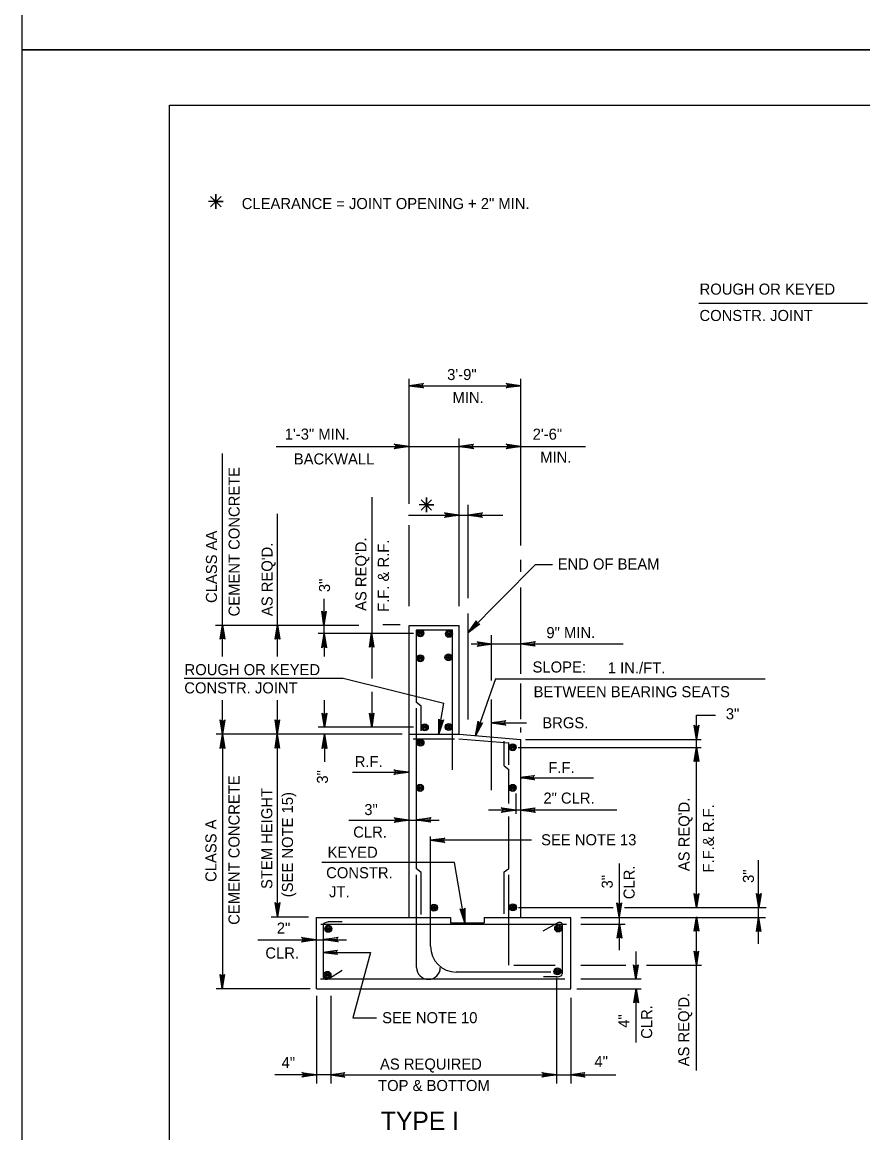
# Model space of a CAD drawing. Extents: x 235 to 2276, y 116 to 1308.
# Drawn here: x 579.4 to 807.5, y 416.6 to 717.9 of the extents above; entities that cross this region are included whole.
import ezdxf

# ---------------------------------------------------------------- set-up
doc = ezdxf.new("R2010")
doc.units = 0
doc.layers.add('1', color=7, linetype='Continuous')
doc.layers.add('PLT-BNDY', color=7, linetype='Continuous')

msp = doc.modelspace()

# ---------------------------------------------------------------- linework, layer by layer
at = {"layer": '1'}
for p, q in [((619.42, 131.41), (619.42, 695.41)), ((619.42, 695.41), (1405.42, 695.41)), ((631.98, 669.26), (631.98, 669.26)), ((763.08, 641.72), (808.83, 641.72)), ((684.4, 587.22), (684.4, 621.18)), ((714.75, 575.95), (714.75, 621.18)), ((684.4, 619.3), (714.75, 619.3)), ((648.36, 602.82), (732.25, 602.82)), ((698.03, 559.47), (698.03, 604.95)), ((633.78, 552.08), (633.78, 600.87)), ((674.26, 589.02), (674.26, 561.61)), ((689.11, 586.94), (689.11, 586.94)), ((700.43, 561.61), (700.43, 586.94)), ((648.68, 552.08), (648.68, 584.55)), ((684.25, 584.19), (709.85, 584.19)), ((684.4, 559.47), (684.4, 581.44)), ((700.43, 552.31), (718.7, 570.82)), ((714.75, 568.8), (714.75, 572.06)), ((718.7, 570.82), (723.35, 570.82)), ((714.75, 541.14), (714.75, 564.57)), ((661.33, 552.08), (661.33, 561.51)), ((674.26, 561.61), (674.26, 550.05)), ((700.43, 528.74), (700.43, 557.53)), ((670.73, 554.27), (631.9, 554.27)), ((633.78, 545.85), (633.78, 554.27)), ((648.68, 545.85), (648.68, 554.27)), ((685.65, 552.08), (659.72, 552.08)), ((661.33, 551.98), (661.33, 545.85)), ((674.26, 552.08), (674.26, 539.83)), ((682, 554.4), (677.25, 554.4)), ((684.4, 475.05), (684.4, 554.27)), ((684.4, 554.27), (698.03, 554.27)), ((686.44, 533.33), (686.44, 553.02)), ((686.44, 553.02), (696.18, 553.02)), ((696.18, 515.05), (696.18, 553.02)), ((698.03, 524.74), (698.03, 554.27)), ((706.78, 539.3), (706.78, 551.65)), ((701.26, 549.22), (742.47, 549.22)), ((623.33, 539.98), (666.56, 539.98)), ((666.56, 539.98), (693.81, 533.18)), ((707.88, 539.74), (781.08, 539.74)), ((714.75, 537.55), (714.75, 538.52)), ((714.75, 528.82), (714.75, 537.55)), ((633.78, 524.74), (633.78, 533.97)), ((648.68, 475.18), (648.68, 533.97)), ((661.44, 526.61), (661.44, 533.97)), ((674.26, 536.25), (674.26, 526.61)), ((687.69, 532.39), (686.44, 533.33)), ((706.78, 509.58), (706.78, 534.14)), ((686.44, 488.18), (686.44, 531.77)), ((687.69, 525.68), (687.69, 532.39)), ((692.41, 524.74), (693.81, 533.18)), ((706.78, 527.8), (716.31, 527.8)), ((762.41, 529.88), (767.54, 529.88)), ((762.41, 521.14), (762.41, 529.88)), ((654.09, 524.74), (632.06, 524.74)), ((633.78, 524.74), (633.78, 455.68)), ((682.53, 524.74), (654.09, 524.74)), ((685.65, 526.61), (659.72, 526.61)), ((661.44, 524.74), (661.44, 517.22)), ((684.4, 524.74), (698.03, 524.74)), ((698.03, 524.74), (714.75, 523.33)), ((714.75, 525.21), (714.75, 526.6)), ((685.5, 523.49), (696.75, 523.49)), ((697.88, 523.49), (711.47, 522.39)), ((710.22, 516.14), (710.22, 522.86)), ((711.47, 516.46), (711.47, 522.39)), ((714.75, 475.05), (714.75, 523.33)), ((716.04, 523.33), (763.66, 523.33)), ((713.97, 521.14), (734.44, 521.14)), ((734.44, 521.14), (763.66, 521.14)), ((762.41, 477.71), (762.41, 521.14)), ((710.22, 516.14), (711.47, 515.21)), ((669.09, 514.43), (684.4, 514.43)), ((711.47, 505.94), (711.47, 515.21)), ((714.75, 512.86), (734.44, 512.86)), ((713.43, 503.17), (713.43, 508.64)), ((713.43, 504.17), (705.92, 504.17)), ((714.75, 504.17), (713.43, 504.17)), ((740.77, 504.17), (714.75, 504.17)), ((668.09, 501.46), (684.4, 501.46)), ((684.4, 501.46), (692.59, 501.46)), ((711.47, 488.33), (711.47, 502.41)), ((690.22, 467.2), (690.22, 497.03)), ((717.59, 495.96), (690.22, 495.96)), ((696.74, 489.89), (660.69, 489.89)), ((687.69, 487.24), (686.44, 488.18)), ((699.51, 473.52), (696.74, 489.89)), ((710.22, 487.39), (711.47, 488.33)), ((741.47, 475.05), (741.47, 489.62)), ((779.28, 477.71), (779.28, 490.54)), ((686.44, 461.46), (686.44, 486.61)), ((687.69, 475.83), (687.69, 487.24)), ((710.22, 475.99), (710.22, 487.39)), ((711.47, 462.08), (711.47, 486.61)), ((714.13, 477.71), (739.75, 477.71)), ((742.88, 477.71), (781.31, 477.71)), ((779.26, 467.9), (779.26, 477.71)), ((646.94, 475.18), (657.14, 475.18)), ((659.25, 455.68), (659.25, 475.05)), ((659.25, 475.05), (695.69, 475.05)), ((660.5, 473.18), (727.1, 473.18)), ((666.28, 473.8), (662.37, 473.8)), ((695.69, 475.05), (695.69, 473.52)), ((695.69, 473.52), (704.75, 473.52)), ((704.75, 475.05), (728.35, 475.05)), ((704.75, 475.05), (704.75, 473.52)), ((724.6, 473.49), (720.69, 471.3)), ((726, 459.74), (726, 473.18)), ((728.35, 455.68), (728.35, 475.05)), ((731.05, 475.05), (781.16, 475.05)), ((731.05, 473.18), (743.03, 473.18)), ((741.47, 466.14), (741.47, 475.05)), ((762.41, 462.08), (762.41, 475.05)), ((661.12, 473.02), (661.12, 458.8)), ((643.41, 468.99), (659.25, 468.99)), ((659.25, 468.99), (667.43, 468.99)), ((661.12, 465.55), (673.9, 465.55)), ((673.9, 465.55), (669.13, 447.75)), ((746, 458.33), (746, 465.83)), ((712.88, 462.08), (724.09, 462.08)), ((731.05, 462.08), (743.19, 462.08)), ((748.81, 462.08), (763.81, 462.08)), ((762.41, 433.47), (762.41, 462.08)), ((660.36, 458.33), (726.65, 458.33)), ((662.53, 458.33), (666.28, 460.68)), ((722.9, 460.2), (697.22, 460.2)), ((720.85, 458.96), (724.6, 458.96)), ((724.44, 458.64), (724.44, 429.95)), ((731.05, 458.33), (747.41, 458.33)), ((654.09, 455.68), (632.06, 455.68)), ((657.53, 455.68), (654.09, 455.68)), ((659.25, 455.68), (728.35, 455.68)), ((729.91, 455.68), (747.41, 455.68)), ((746, 441.14), (746, 455.68)), ((659.25, 453.8), (659.25, 429.95)), ((663.15, 453.8), (663.15, 429.95)), ((728.35, 453.26), (728.35, 429.95)), ((669.13, 447.75), (675.53, 447.75)), ((663.15, 432.31), (647.94, 432.31)), ((664.44, 432.31), (724.44, 432.31)), ((724.44, 432.31), (740.49, 432.31))]:
    msp.add_line(p, q, dxfattribs=at)
for points in [[(633.39, 670.67), (630.56, 667.84), (631.98, 669.26), (633.39, 667.84), (630.56, 670.67), (631.98, 669.26), (631.98, 671.26), (631.98, 667.26), (631.98, 669.26), (633.98, 669.26), (629.98, 669.26)], [(688.15, 618.8), (688.03, 619.05), (684.4, 619.3), (688.15, 618.8), (688.28, 618.68), (684.4, 619.3), (688.03, 619.43), (688.15, 619.8), (684.4, 619.3), (688.28, 619.93), (688.15, 619.8)], [(711, 619.8), (711.13, 619.55), (714.75, 619.3), (711, 619.8), (710.75, 619.93), (714.75, 619.3), (711.13, 619.18), (711, 618.93), (714.75, 619.3), (710.75, 618.68), (711, 618.93)], [(680.65, 603.32), (680.78, 603.07), (684.4, 602.82), (680.65, 603.32), (680.4, 603.45), (684.4, 602.82), (680.78, 602.7), (680.65, 602.45), (684.4, 602.82), (680.4, 602.2), (680.65, 602.45)], [(701.78, 602.32), (701.66, 602.57), (698.03, 602.82), (701.78, 602.32), (701.91, 602.2), (698.03, 602.82), (701.66, 602.95), (701.78, 603.32), (698.03, 602.82), (701.91, 603.45), (701.78, 603.32)], [(711, 603.32), (711.13, 603.07), (714.75, 602.82), (711, 603.32), (710.75, 603.45), (714.75, 602.82), (711.13, 602.7), (711, 602.45), (714.75, 602.82), (710.75, 602.2), (711, 602.45)], [(690.53, 588.36), (687.7, 585.53), (689.11, 586.94), (690.53, 585.53), (687.7, 588.36), (689.11, 586.94), (689.11, 588.94), (689.11, 584.94), (689.11, 586.94), (691.11, 586.94), (687.11, 586.94)], [(694.28, 584.69), (694.41, 584.44), (698.03, 584.19), (694.28, 584.69), (694.03, 584.81), (698.03, 584.19), (694.41, 584.06), (694.28, 583.81), (698.03, 584.19), (694.03, 583.56), (694.28, 583.81)], [(704.18, 583.69), (704.06, 583.94), (700.43, 584.19), (704.18, 583.69), (704.31, 583.56), (700.43, 584.19), (704.06, 584.31), (704.18, 584.69), (700.43, 584.19), (704.31, 584.81), (704.18, 584.69)], [(661.82, 557.98), (661.57, 557.73), (661.32, 554.23), (661.82, 557.98), (661.95, 558.11), (661.32, 554.23), (661.2, 557.73), (660.95, 557.86), (661.32, 554.23), (660.7, 558.11), (660.95, 557.86)], [(633.28, 550.67), (633.53, 550.8), (633.78, 554.42), (633.28, 550.67), (633.15, 550.55), (633.78, 554.42), (633.9, 550.8), (634.28, 550.67), (633.78, 554.42), (634.4, 550.55), (634.28, 550.67)], [(703.42, 554.63), (703.16, 554.71), (700.43, 552.31), (703.42, 554.63), (703.6, 554.63), (700.43, 552.31), (702.89, 554.98), (702.71, 555.33), (700.43, 552.31), (702.71, 555.51), (702.71, 555.33)], [(648.18, 550.64), (648.43, 550.76), (648.68, 554.39), (648.18, 550.64), (648.05, 550.51), (648.68, 554.39), (648.8, 550.76), (649.18, 550.64), (648.68, 554.39), (649.3, 550.51), (649.18, 550.64)], [(660.88, 548.33), (661.13, 548.46), (661.38, 552.08), (660.88, 548.33), (660.76, 548.21), (661.38, 552.08), (661.51, 548.46), (661.88, 548.33), (661.38, 552.08), (662.01, 548.21), (661.88, 548.33)], [(673.75, 548.45), (674, 548.57), (674.25, 552.2), (673.75, 548.45), (673.63, 548.32), (674.25, 552.2), (674.38, 548.57), (674.75, 548.45), (674.25, 552.2), (674.88, 548.32), (674.75, 548.45)], [(703.12, 549.71), (703.25, 549.46), (706.87, 549.21), (703.12, 549.71), (702.87, 549.83), (706.87, 549.21), (703.25, 549.08), (703.12, 548.83), (706.87, 549.21), (702.87, 548.58), (703.12, 548.83)], [(718.5, 548.72), (718.38, 548.97), (714.75, 549.22), (718.5, 548.72), (718.63, 548.6), (714.75, 549.22), (718.38, 549.35), (718.5, 549.72), (714.75, 549.22), (718.63, 549.85), (718.5, 549.72)], [(707.88, 539.74), (702.41, 524.27)], [(661.93, 530.33), (661.68, 530.08), (661.43, 526.58), (661.93, 530.33), (662.05, 530.45), (661.43, 526.58), (661.3, 530.08), (661.05, 530.2), (661.43, 526.58), (660.8, 530.45), (661.05, 530.2)], [(674.77, 530.33), (674.52, 530.08), (674.27, 526.58), (674.77, 530.33), (674.89, 530.45), (674.27, 526.58), (674.14, 530.08), (673.89, 530.2), (674.27, 526.58), (673.64, 530.45), (673.89, 530.2)], [(634.28, 528.49), (634.03, 528.24), (633.78, 524.74), (634.28, 528.49), (634.4, 528.61), (633.78, 524.74), (633.65, 528.24), (633.4, 528.36), (633.78, 524.74), (633.15, 528.61), (633.4, 528.36)], [(649.15, 528.54), (648.9, 528.29), (648.65, 524.79), (649.15, 528.54), (649.28, 528.67), (648.65, 524.79), (648.53, 528.29), (648.28, 528.42), (648.65, 524.79), (648.03, 528.67), (648.28, 528.42)], [(693.54, 528.49), (693.24, 528.4), (692.45, 524.84), (693.54, 528.49), (693.73, 528.66), (692.45, 524.84), (692.87, 528.46), (692.62, 528.63), (692.45, 524.84), (692.48, 528.86), (692.62, 528.63)], [(704.12, 527.72), (703.82, 527.68), (702.41, 524.32), (704.12, 527.72), (704.34, 527.85), (702.41, 524.32), (703.46, 527.8), (703.25, 528.02), (702.41, 524.32), (703.14, 528.27), (703.25, 528.02)], [(710.52, 527.31), (710.39, 527.56), (706.77, 527.81), (710.52, 527.31), (710.64, 527.19), (706.77, 527.81), (710.39, 527.94), (710.52, 528.31), (706.77, 527.81), (710.64, 528.44), (710.52, 528.31)], [(633.28, 520.99), (633.53, 521.11), (633.78, 524.74), (633.28, 520.99), (633.15, 520.86), (633.78, 524.74), (633.9, 521.11), (634.28, 520.99), (633.78, 524.74), (634.4, 520.86), (634.28, 520.99)], [(648.15, 521.04), (648.4, 521.17), (648.65, 524.79), (648.15, 521.04), (648.03, 520.92), (648.65, 524.79), (648.78, 521.17), (649.15, 521.04), (648.65, 524.79), (649.28, 520.92), (649.15, 521.04)], [(660.94, 520.99), (661.19, 521.11), (661.44, 524.74), (660.94, 520.99), (660.81, 520.86), (661.44, 524.74), (661.56, 521.11), (661.94, 520.99), (661.44, 524.74), (662.06, 520.86), (661.94, 520.99)], [(762.91, 527.08), (762.66, 526.83), (762.41, 523.33), (762.91, 527.08), (763.03, 527.21), (762.41, 523.33), (762.28, 526.83), (762.03, 526.96), (762.41, 523.33), (761.78, 527.21), (762.03, 526.96)], [(761.93, 517.43), (762.18, 517.56), (762.43, 521.18), (761.93, 517.43), (761.8, 517.31), (762.43, 521.18), (762.55, 517.56), (762.93, 517.43), (762.43, 521.18), (763.05, 517.31), (762.93, 517.43)], [(680.51, 514.91), (680.64, 514.66), (684.26, 514.41), (680.51, 514.91), (680.26, 515.03), (684.26, 514.41), (680.64, 514.28), (680.51, 514.03), (684.26, 514.41), (680.26, 513.78), (680.51, 514.03)], [(718.29, 512.45), (718.17, 512.7), (714.54, 512.95), (718.29, 512.45), (718.42, 512.32), (714.54, 512.95), (718.17, 513.07), (718.29, 513.45), (714.54, 512.95), (718.42, 513.57), (718.29, 513.45)], [(709.68, 504.67), (709.8, 504.42), (713.43, 504.17), (709.68, 504.67), (709.43, 504.79), (713.43, 504.17), (709.8, 504.04), (709.68, 503.79), (713.43, 504.17), (709.43, 503.54), (709.68, 503.79)], [(718.5, 503.67), (718.38, 503.92), (714.75, 504.17), (718.5, 503.67), (718.63, 503.54), (714.75, 504.17), (718.38, 504.29), (718.5, 504.67), (714.75, 504.17), (718.63, 504.79), (718.5, 504.67)], [(680.63, 501.95), (680.76, 501.7), (684.38, 501.45), (680.63, 501.95), (680.38, 502.08), (684.38, 501.45), (680.76, 501.33), (680.63, 501.08), (684.38, 501.45), (680.38, 500.83), (680.63, 501.08)], [(690.18, 500.97), (690.05, 501.22), (686.43, 501.47), (690.18, 500.97), (690.3, 500.85), (686.43, 501.47), (690.05, 501.6), (690.18, 501.97), (686.43, 501.47), (690.3, 502.1), (690.18, 501.97)], [(693.97, 495.46), (693.85, 495.71), (690.22, 495.96), (693.97, 495.46), (694.1, 495.33), (690.22, 495.96), (693.85, 496.08), (693.97, 496.46), (690.22, 495.96), (694.1, 496.58), (693.97, 496.46)], [(762.92, 481.4), (762.67, 481.15), (762.42, 477.65), (762.92, 481.4), (763.04, 481.52), (762.42, 477.65), (762.29, 481.15), (762.04, 481.27), (762.42, 477.65), (761.79, 481.52), (762.04, 481.27)], [(779.8, 481.39), (779.55, 481.14), (779.3, 477.64), (779.8, 481.39), (779.93, 481.51), (779.3, 477.64), (779.18, 481.14), (778.93, 481.26), (779.3, 477.64), (778.68, 481.51), (778.93, 481.26)], [(649.18, 478.93), (648.93, 478.68), (648.68, 475.18), (649.18, 478.93), (649.31, 479.06), (648.68, 475.18), (648.56, 478.68), (648.31, 478.81), (648.68, 475.18), (648.06, 479.06), (648.31, 478.81)], [(699.4, 477.33), (699.15, 477.15), (699.51, 473.52), (699.4, 477.33), (699.53, 477.55), (699.51, 473.52), (698.77, 477.09), (698.49, 477.18), (699.51, 473.52), (698.28, 477.35), (698.49, 477.18)], [(741.91, 478.84), (741.66, 478.59), (741.41, 475.09), (741.91, 478.84), (742.04, 478.97), (741.41, 475.09), (741.29, 478.59), (741.04, 478.72), (741.41, 475.09), (740.79, 478.97), (741.04, 478.72)], [(740.99, 469.55), (741.24, 469.67), (741.49, 473.3), (740.99, 469.55), (740.87, 469.42), (741.49, 473.3), (741.62, 469.67), (741.99, 469.55), (741.49, 473.3), (742.12, 469.42), (741.99, 469.55)], [(761.94, 471.42), (762.19, 471.55), (762.44, 475.17), (761.94, 471.42), (761.82, 471.3), (762.44, 475.17), (762.57, 471.55), (762.94, 471.42), (762.44, 475.17), (763.07, 471.3), (762.94, 471.42)], [(778.78, 471.3), (779.03, 471.43), (779.28, 475.05), (778.78, 471.3), (778.66, 471.18), (779.28, 475.05), (779.41, 471.43), (779.78, 471.3), (779.28, 475.05), (779.91, 471.18), (779.78, 471.3)], [(655.48, 469.48), (655.6, 469.23), (659.23, 468.98), (655.48, 469.48), (655.23, 469.61), (659.23, 468.98), (655.6, 468.86), (655.48, 468.61), (659.23, 468.98), (655.23, 468.36), (655.48, 468.61)], [(665.02, 468.51), (664.9, 468.76), (661.27, 469.01), (665.02, 468.51), (665.15, 468.38), (661.27, 469.01), (664.9, 469.13), (665.02, 469.51), (661.27, 469.01), (665.15, 469.63), (665.02, 469.51)], [(664.87, 465.05), (664.75, 465.3), (661.12, 465.55), (664.87, 465.05), (665, 464.93), (661.12, 465.55), (664.75, 465.68), (664.87, 466.05), (661.12, 465.55), (665, 466.18), (664.87, 466.05)], [(762.87, 465.79), (762.62, 465.54), (762.37, 462.04), (762.87, 465.79), (762.99, 465.92), (762.37, 462.04), (762.24, 465.54), (761.99, 465.67), (762.37, 462.04), (761.74, 465.92), (761.99, 465.67)], [(746.46, 462.04), (746.21, 461.79), (745.96, 458.29), (746.46, 462.04), (746.59, 462.17), (745.96, 458.29), (745.84, 461.79), (745.59, 461.92), (745.96, 458.29), (745.34, 462.17), (745.59, 461.92)], [(634.23, 459.47), (633.98, 459.22), (633.73, 455.72), (634.23, 459.47), (634.36, 459.59), (633.73, 455.72), (633.61, 459.22), (633.36, 459.34), (633.73, 455.72), (633.11, 459.59), (633.36, 459.34)], [(745.53, 452.02), (745.78, 452.15), (746.03, 455.77), (745.53, 452.02), (745.41, 451.9), (746.03, 455.77), (746.16, 452.15), (746.53, 452.02), (746.03, 455.77), (746.66, 451.9), (746.53, 452.02)], [(655.55, 432.81), (655.67, 432.56), (659.3, 432.31), (655.55, 432.81), (655.3, 432.93), (659.3, 432.31), (655.67, 432.18), (655.55, 431.93), (659.3, 432.31), (655.3, 431.68), (655.55, 431.93)], [(666.83, 431.79), (666.71, 432.04), (663.08, 432.29), (666.83, 431.79), (666.96, 431.67), (663.08, 432.29), (666.71, 432.42), (666.83, 432.79), (663.08, 432.29), (666.96, 432.92), (666.83, 432.79)], [(720.68, 432.82), (720.8, 432.57), (724.43, 432.32), (720.68, 432.82), (720.43, 432.95), (724.43, 432.32), (720.8, 432.2), (720.68, 431.95), (724.43, 432.32), (720.43, 431.7), (720.68, 431.95)], [(732.03, 431.83), (731.9, 432.08), (728.28, 432.33), (732.03, 431.83), (732.15, 431.71), (728.28, 432.33), (731.9, 432.46), (732.03, 432.83), (728.28, 432.33), (732.15, 432.96), (732.03, 432.83)]]:
    msp.add_lwpolyline(points, dxfattribs=at)
for centre, radius in [((687.47, 552.13), 0.954), ((687.47, 552.13), 0.681), ((687.47, 552.13), 0.372), ((687.47, 552.13), 0.188), ((687.47, 552.13), 0.0805), ((695.24, 551.99), 0.954), ((695.24, 551.99), 0.681), ((695.24, 551.99), 0.372), ((695.24, 551.99), 0.188), ((695.24, 551.99), 0.0805), ((687.45, 545.35), 0.954), ((687.45, 545.35), 0.681), ((687.45, 545.35), 0.372), ((687.45, 545.35), 0.188), ((687.45, 545.35), 0.0805), ((695.11, 545.6), 0.954), ((695.11, 545.6), 0.681), ((695.11, 545.6), 0.372), ((695.11, 545.6), 0.188), ((695.11, 545.6), 0.0805), ((688.67, 526.62), 0.954), ((695.18, 526.7), 0.954), ((695.18, 526.7), 0.681), ((688.67, 526.62), 0.681), ((688.67, 526.62), 0.372), ((688.67, 526.62), 0.188), ((688.67, 526.62), 0.0805), ((695.18, 526.7), 0.372), ((695.18, 526.7), 0.188), ((695.18, 526.7), 0.0805), ((687.49, 522.48), 0.954), ((687.49, 522.48), 0.681), ((687.49, 522.48), 0.372), ((687.49, 522.48), 0.188), ((687.49, 522.48), 0.0805), ((712.53, 521.19), 0.954), ((712.53, 521.19), 0.681), ((712.53, 521.19), 0.372), ((712.53, 521.19), 0.188), ((712.53, 521.19), 0.0805), ((687.38, 510.19), 0.954), ((687.38, 510.19), 0.681), ((687.38, 510.19), 0.372), ((687.38, 510.19), 0.188), ((687.38, 510.19), 0.0805), ((712.54, 510.18), 0.954), ((712.54, 510.18), 0.681), ((712.54, 510.18), 0.372), ((712.54, 510.18), 0.188), ((712.54, 510.18), 0.0805), ((691.15, 477.67), 0.954), ((691.15, 477.67), 0.681), ((691.15, 477.67), 0.372), ((691.15, 477.67), 0.188), ((691.15, 477.67), 0.0805), ((712.6, 477.76), 0.954), ((712.6, 477.76), 0.681), ((712.6, 477.76), 0.372), ((712.6, 477.76), 0.188), ((712.6, 477.76), 0.0805), ((662.48, 471.95), 0.954), ((662.48, 471.95), 0.681), ((662.48, 471.95), 0.372), ((662.48, 471.95), 0.188), ((662.48, 471.95), 0.0805), ((724.88, 472.04), 0.954), ((724.88, 472.04), 0.681), ((724.88, 472.04), 0.372), ((724.88, 472.04), 0.188), ((724.88, 472.04), 0.0805), ((724.67, 460.39), 0.954), ((724.67, 460.39), 0.681), ((662.26, 459.45), 0.954), ((662.26, 459.45), 0.681), ((662.26, 459.45), 0.372), ((662.26, 459.45), 0.188), ((662.26, 459.45), 0.0805), ((724.67, 460.39), 0.372), ((724.67, 460.39), 0.188), ((724.67, 460.39), 0.0805)]:
    msp.add_circle(centre, radius, dxfattribs=at)
for centre, radius, end in [((697.22, 467.2), 7, 270), ((689.66, 461.46), 3.22, 0)]:
    msp.add_arc(centre, radius, 180, end, dxfattribs=at)
for centre, major_axis, ratio, start_param, end_param in [((662.42, 472.96), (-1.3, 0), 0.602565, 4.712389, 6.283185), ((725.16, 473.18), (-0.812, 0), 0.572437, 3.141593, 5.497787), ((661.93, 458.75), (0.812, 0), 0.602565, 3.141593, 5.497787), ((724.67, 459.69), (1.3, 0), 0.572437, 4.712389, 6.283185)]:
    msp.add_ellipse(centre, major_axis=major_axis, ratio=ratio, start_param=start_param, end_param=end_param, dxfattribs=at)
at = {"layer": 'PLT-BNDY'}
for points in [[(579.42, 1304.41), (1420.42, 1304.41), (1420.42, 710.41), (579.42, 710.41)], [(579.42, 710.41), (1420.42, 710.41), (1420.42, 116.41), (579.42, 116.41)]]:
    msp.add_lwpolyline(points, close=True, dxfattribs=at)

# ---------------------------------------------------------------- texts
at = {"layer": '1'}
for s, height, p in [('CLEARANCE = JOINT OPENING + 2" MIN.', 3, (639, 667.22)), ('ROUGH OR KEYED', 3, (763.25, 644)), ('CONSTR. JOINT', 3, (763.22, 636.85)), ('3\'-9"', 3.003, (694.74, 620.83)), ('MIN.', 3, (696.2, 614.59)), ('1\'-3" MIN.', 3.003, (650.67, 604.66)), ('2\'-6"', 3.003, (717.95, 604.64)), ('BACKWALL', 3, (653.13, 597.93)), ('MIN.', 3, (719.99, 598.4)), ('END OF BEAM', 3, (724.73, 569.42)), ('9" MIN.', 3.003, (721.67, 550.8)), ('ROUGH OR KEYED', 3, (623.48, 540.76)), ('SLOPE:', 3, (717.92, 541.48)), ('1 IN./FT.', 3.003, (738.33, 541.25)), ('CONSTR. JOINT', 3, (623.41, 535.81)), ('BETWEEN BEARING SEATS', 3, (718.2, 534.77)), ('3"', 3.003, (770.37, 528.78)), ('  BRGS.', 3, (718.34, 526.34)), ('R.F.', 3, (669.66, 515.81)), ('F.F.', 3, (722.21, 514.19)), ('2" CLR.', 3, (720.86, 505.91)), ('3"', 3.003, (672.25, 502.79)), ('CLR.', 3, (669.25, 496.69)), ('SEE NOTE 13', 3, (720.24, 494.61)), ('KEYED ', 3, (662.3, 491.21)), ('CONSTR. ', 3, (661.91, 485.66)), ('JT.', 3, (662.7, 480.5)), ('2"', 3.003, (648.51, 470.64)), ('CLR.', 3, (645.41, 463.88)), ('SEE NOTE 10', 3, (677.1, 446.33)), ('4"', 3.003, (649.82, 434.15)), ('4"', 3.003, (734.71, 434.43)), (' AS REQUIRED ', 3, (675.41, 433.75)), ('TOP & BOTTOM', 3, (676, 427.93)), (' TYPE I', 5, (674.91, 417.33))]:
    msp.add_text(s, height=height, dxfattribs=at).set_placement(p)
for s, p in [('CEMENT CONCRETE', (638.43, 556.7)), ('CLASS AA', (632.28, 560.34)), ("AS REQ'D.", (647.37, 556.78)), ("AS REQ'D.", (672.84, 558.19)), ('F.F. & R.F.', (678.93, 557.93)), ('3"', (662.96, 563.29)), ('CEMENT CONCRETE', (638.4, 473.03)), ('3"', (662.39, 511.33)), ('STEM HEIGHT', (647.29, 482.75)), ('(SEE NOTE 15)', (652.91, 480.51)), ("AS REQ'D.", (760.52, 487.58)), ('F.F.& R.F.', (767.13, 487.23)), ('CLASS A', (632.14, 484.66)), ('CLR.', (745.62, 479.97)), ('3"', (739.67, 482.9)), ('3"', (777.99, 484.39)), ("AS REQ'D.", (760.44, 434.63)), ('CLR.', (750.38, 442.09)), ('4"', (744.18, 445.09))]:
    msp.add_text(s, height=3, rotation=90, dxfattribs=at).set_placement(p)

doc.saveas('drawing.dxf')
